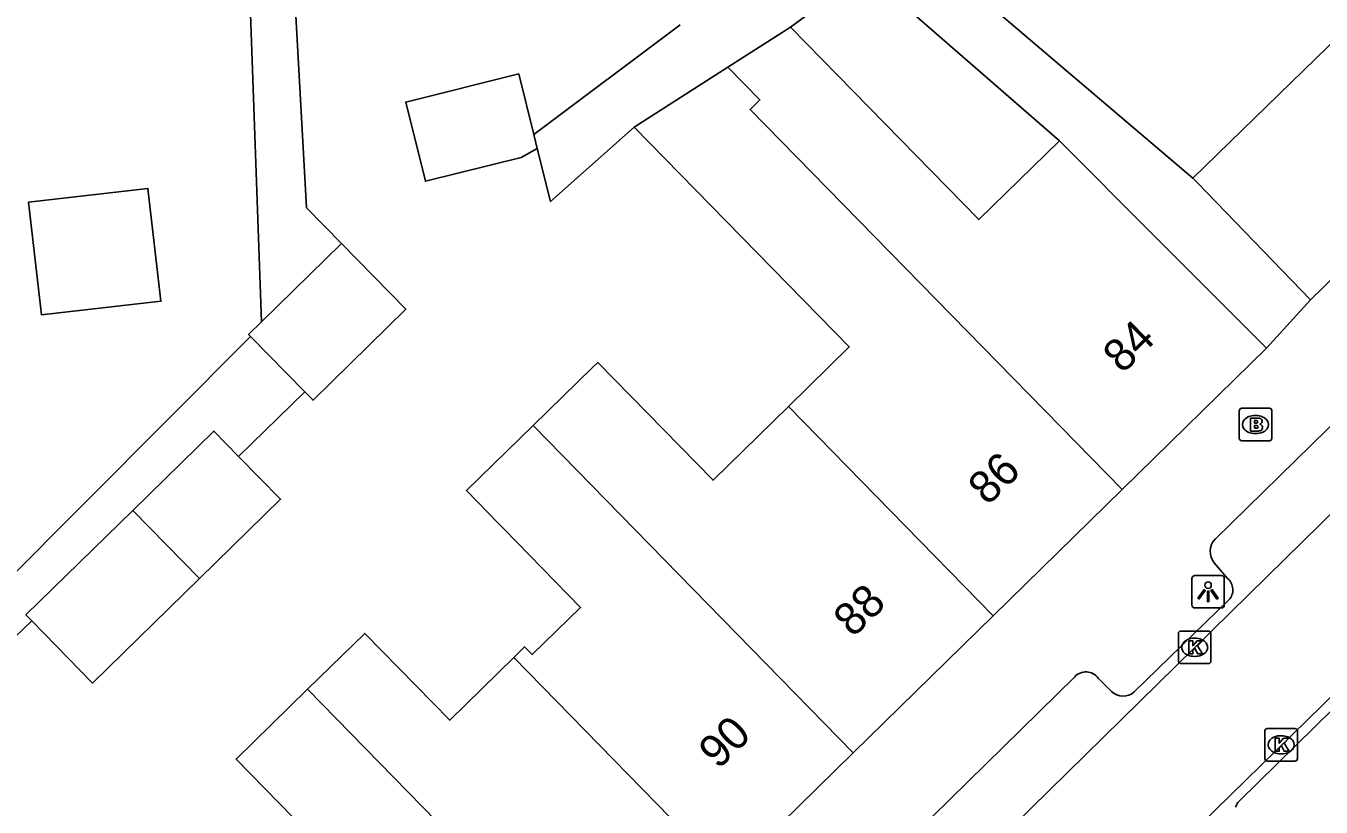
# Model space of a CAD drawing. Extents: x 160861 to 161308, y 384024 to 384878.
# Drawn here: x 161043.45 to 161083.27, y 384669.26 to 384693.28 of the extents above; entities that cross this region are included whole.
import ezdxf

# ---------------------------------------------------------------- set-up
doc = ezdxf.new("R2010")
doc.units = 0
for name, color, linetype in [('IMGEO_Brandkraan', 7, 'Continuous'), ('IMGEO_Kolk', 7, 'Continuous'), ('IMGEO_Lichtpunt', 7, 'Continuous'), ('IMGEO_Pand', 7, 'Continuous'), ('IMGEO_Pand_nummerreeks', 7, 'Continuous'), ('IMGEO_Rijbaan_lokaal_gesloten', 7, 'Continuous'), ('IMGEO_Voetpad_open', 7, 'Continuous')]:
    doc.layers.add(name, color=color, linetype=linetype)

msp = doc.modelspace()

# ---------------------------------------------------------------- linework, layer by layer
at = {"layer": 'IMGEO_Brandkraan'}
for p, q in [((161080.753, 384680.596), (161080.753, 384681.448)), ((161080.828, 384681.522), (161081.68, 384681.522)), ((161081.754, 384681.448), (161081.754, 384680.596)), ((161081.241, 384681.302), (161081.266, 384681.302)), ((161081.264, 384680.742), (161081.239, 384680.742)), ((161081.68, 384680.522), (161080.828, 384680.522))]:
    msp.add_line(p, q, dxfattribs=at)
for points in [[(161080.753, 384680.596), (161080.753, 384681.448)], [(161080.828, 384681.522), (161081.68, 384681.522)], [(161081.754, 384681.448), (161081.754, 384680.596)], [(161081.101, 384681.222), (161081.101, 384680.822), (161081.314, 384680.822)], [(161081.332, 384681.222), (161081.101, 384681.222)], [(161081.28, 384681.141), (161081.226, 384681.141), (161081.226, 384681.065)], [(161081.226, 384681.065), (161081.279, 384681.065)], [(161081.288, 384680.989), (161081.226, 384680.989), (161081.226, 384680.908)], [(161081.226, 384680.908), (161081.288, 384680.908)], [(161081.68, 384680.522), (161080.828, 384680.522)]]:
    msp.add_lwpolyline(points, dxfattribs=at)
for centre, radius, start, end in [((161080.83, 384681.446), 0.0765, 91.552, 178.448), ((161080.83, 384681.446), 0.0765, 91.552, 178.448), ((161081.678, 384681.446), 0.0765, 1.552, 88.448), ((161081.678, 384681.446), 0.0765, 1.552, 88.448), ((161081.281, 384681.103), 0.0379, 267.8285, 90.9355), ((161081.336, 384681.077), 0.145, 59.4692, 91.5367), ((161081.361, 384681.124), 0.0922, 285.5137, 58.1501), ((161081.366, 384680.932), 0.105, 301.3115, 78.989), ((161080.83, 384680.598), 0.0765, 181.552, 268.448), ((161080.83, 384680.598), 0.0765, 181.552, 268.448), ((161081.289, 384680.948), 0.0404, 269.8759, 90.5077), ((161081.32, 384681.073), 0.251, 268.6676, 293.5347), ((161081.678, 384680.598), 0.0765, 271.552, 358.448), ((161081.678, 384680.598), 0.0765, 271.552, 358.448)]:
    msp.add_arc(centre, radius, start, end, dxfattribs=at)
for centre, major_axis, ratio, start_param, end_param in [((161081.24, 384681.022), (-0.387, 0.002), 0.722429, 4.712389, 7.853982), ((161081.265, 384681.022), (-0.39, 0.002), 0.717154, 1.570796, 4.712389)]:
    msp.add_ellipse(centre, major_axis=major_axis, ratio=ratio, start_param=start_param, end_param=end_param, dxfattribs=at)
at = {"layer": 'IMGEO_Kolk'}
for p, q in [((161078.956, 384674.674), (161079.808, 384674.674)), ((161078.881, 384673.748), (161078.881, 384674.6)), ((161079.369, 384674.454), (161079.394, 384674.454)), ((161079.882, 384674.6), (161079.882, 384673.748)), ((161079.392, 384673.894), (161079.367, 384673.894)), ((161079.808, 384673.674), (161078.956, 384673.674)), ((161081.539, 384670.751), (161081.539, 384671.603)), ((161081.614, 384671.677), (161082.466, 384671.677)), ((161082.027, 384671.457), (161082.052, 384671.457)), ((161082.54, 384671.603), (161082.54, 384670.751)), ((161082.466, 384670.677), (161081.614, 384670.677)), ((161082.05, 384670.897), (161082.025, 384670.897))]:
    msp.add_line(p, q, dxfattribs=at)
for points in [[(161078.956, 384674.674), (161079.808, 384674.674)], [(161078.881, 384673.748), (161078.881, 384674.6)], [(161079.202, 384674.374), (161079.325, 384674.374), (161079.325, 384674.223), (161079.455, 384674.374), (161079.619, 384674.374), (161079.473, 384674.223), (161079.626, 384673.974), (161079.474, 384673.974), (161079.389, 384674.138), (161079.325, 384674.071), (161079.325, 384673.974), (161079.202, 384673.974), (161079.202, 384674.374)], [(161079.882, 384674.6), (161079.882, 384673.748)], [(161079.808, 384673.674), (161078.956, 384673.674)], [(161081.539, 384670.751), (161081.539, 384671.603)], [(161081.614, 384671.677), (161082.466, 384671.677)], [(161082.54, 384671.603), (161082.54, 384670.751)], [(161081.86, 384671.377), (161081.983, 384671.377), (161081.983, 384671.226), (161082.113, 384671.377), (161082.277, 384671.377), (161082.131, 384671.226), (161082.284, 384670.977), (161082.132, 384670.977), (161082.047, 384671.141), (161081.983, 384671.074), (161081.983, 384670.977), (161081.86, 384670.977), (161081.86, 384671.377)], [(161082.466, 384670.677), (161081.614, 384670.677)]]:
    msp.add_lwpolyline(points, dxfattribs=at)
for centre, start, end in [((161078.958, 384674.598), 91.552, 178.448), ((161078.958, 384674.598), 91.552, 178.448), ((161079.806, 384674.598), 1.552, 88.448), ((161079.806, 384674.598), 1.552, 88.448), ((161078.958, 384673.75), 181.552, 268.448), ((161078.958, 384673.75), 181.552, 268.448), ((161079.806, 384673.75), 271.552, 358.448), ((161079.806, 384673.75), 271.552, 358.448), ((161081.616, 384671.601), 91.552, 178.448), ((161081.616, 384671.601), 91.552, 178.448), ((161082.464, 384671.601), 1.552, 88.448), ((161082.464, 384671.601), 1.552, 88.448), ((161081.616, 384670.753), 181.552, 268.448), ((161081.616, 384670.753), 181.552, 268.448), ((161082.464, 384670.753), 271.552, 358.448), ((161082.464, 384670.753), 271.552, 358.448)]:
    msp.add_arc(centre, 0.0765, start, end, dxfattribs=at)
for centre, major_axis, ratio, start_param, end_param in [((161079.368, 384674.174), (-0.387, 0.002), 0.722429, 4.712389, 7.853982), ((161079.393, 384674.174), (-0.39, 0.002), 0.717154, 1.570796, 4.712389), ((161082.026, 384671.177), (-0.387, 0.002), 0.722429, 4.712389, 7.853982), ((161082.051, 384671.177), (-0.39, 0.002), 0.717154, 1.570796, 4.712389)]:
    msp.add_ellipse(centre, major_axis=major_axis, ratio=ratio, start_param=start_param, end_param=end_param, dxfattribs=at)
at = {"layer": 'IMGEO_Lichtpunt'}
for p, q in [((161079.295, 384676.285), (161079.295, 384675.478)), ((161079.295, 384676.285), (161079.295, 384675.478)), ((161080.197, 384676.38), (161079.389, 384676.38)), ((161080.197, 384676.38), (161079.389, 384676.38)), ((161080.291, 384675.478), (161080.291, 384676.285)), ((161080.291, 384675.478), (161080.291, 384676.285)), ((161079.389, 384675.384), (161080.197, 384675.384)), ((161079.389, 384675.384), (161080.197, 384675.384))]:
    msp.add_line(p, q, dxfattribs=at)
for points in [[(161079.669, 384675.949), (161079.708, 384675.921), (161079.52, 384675.659), (161079.482, 384675.686), (161079.669, 384675.949)], [(161079.771, 384675.901), (161079.818, 384675.901), (161079.818, 384675.579), (161079.771, 384675.579), (161079.771, 384675.901)], [(161079.881, 384675.921), (161079.919, 384675.948), (161080.106, 384675.686), (161080.067, 384675.658), (161079.881, 384675.921)]]:
    msp.add_lwpolyline(points, dxfattribs=at)
msp.add_circle((161079.794, 384676.083), 0.0994, dxfattribs=at)
for centre, start, end in [((161079.389, 384676.285), 90, 180), ((161079.389, 384676.285), 90, 180), ((161080.197, 384676.285), 0, 90), ((161080.197, 384676.285), 0, 90), ((161079.389, 384675.478), 180, 270), ((161079.389, 384675.478), 180, 270), ((161080.197, 384675.478), 270, 0), ((161080.197, 384675.478), 270, 360)]:
    msp.add_arc(centre, 0.0946, start, end, dxfattribs=at)
at = {"layer": 'IMGEO_Pand'}
for points in [[(161079.327, 384688.593), (161085.753, 384694.857)], [(161065.029, 384692.007), (161066.956, 384693.238)], [(161075.224, 384689.747), (161072.745, 384687.321), (161066.956, 384693.238)], [(161059.169, 384689.512), (161058.674, 384689.231), (161055.728, 384688.499), (161055.124, 384690.935), (161058.601, 384691.798), (161059.064, 384689.933)], [(161062.151, 384690.167), (161065.029, 384692.007)], [(161077.149, 384679.021), (161065.713, 384690.71), (161066.012, 384691.003), (161065.029, 384692.007)], [(161089.608, 384691.356), (161082.942, 384684.859)], [(161066.889, 384681.575), (161068.763, 384683.409), (161062.151, 384690.167)], [(161059.169, 384689.512), (161059.064, 384689.933)], [(161075.224, 384689.747), (161078.057, 384686.906), (161081.588, 384683.366)], [(161082.942, 384684.859), (161079.464, 384688.452), (161079.327, 384688.593)], [(161043.53, 384687.858), (161043.927, 384684.394), (161047.595, 384684.814), (161047.199, 384688.278), (161043.53, 384687.858)], [(161050.691, 384684.181), (161053.148, 384686.588)], [(161052.017, 384682.032), (161052.277, 384681.767), (161055.131, 384684.564), (161053.148, 384686.588)], [(161050.691, 384684.181), (161050.293, 384683.791), (161050.355, 384683.728)], [(161050.355, 384683.728), (161052.017, 384682.032)], [(161081.588, 384683.366), (161077.149, 384679.021)], [(161059.041, 384680.994), (161060.87, 384682.777), (161061.029, 384682.932), (161064.573, 384679.31), (161066.889, 384681.575)], [(161073.184, 384675.14), (161066.889, 384681.575)], [(161058.443, 384673.858), (161058.78, 384674.188), (161059.015, 384673.948), (161060.501, 384675.402), (161058.14, 384677.815), (161057.966, 384677.993), (161056.988, 384678.993), (161059.041, 384680.994)], [(161059.041, 384680.994), (161068.886, 384670.932)], [(161049.984, 384680.044), (161049.227, 384680.819), (161046.73, 384678.379)], [(161049.984, 384680.044), (161051.275, 384678.723), (161048.779, 384676.285)], [(161077.149, 384679.021), (161073.184, 384675.14)], [(161046.73, 384678.379), (161043.447, 384675.172), (161043.624, 384674.991)], [(161048.779, 384676.285), (161046.73, 384678.379)], [(161043.624, 384674.991), (161045.495, 384673.076), (161048.779, 384676.285)], [(161073.184, 384675.14), (161068.886, 384670.932)], [(161052.106, 384672.884), (161053.863, 384674.603), (161056.476, 384671.933), (161058.443, 384673.858)], [(161058.443, 384673.858), (161065.015, 384667.142)], [(161050.828, 384666.256), (161052.547, 384668.039), (161049.91, 384670.735), (161052.106, 384672.884)], [(161052.106, 384672.884), (161060.941, 384663.854)], [(161068.886, 384670.932), (161065.015, 384667.142)]]:
    msp.add_lwpolyline(points, dxfattribs=at)
at = {"layer": 'IMGEO_Rijbaan_lokaal_gesloten'}
for points in [[(161094.179, 384688.665), (161093.847, 384688.359), (161047.62, 384642.996), (161045.943, 384641.353)], [(161048.906, 384638.739), (161096.984, 384685.767)]]:
    msp.add_lwpolyline(points, dxfattribs=at)
at = {"layer": 'IMGEO_Voetpad_open'}
for points in [[(161050.004, 384703.409), (161050.691, 384684.181)], [(161053.148, 384686.588), (161052.077, 384687.681), (161051.522, 384697.663)], [(161079.327, 384688.593), (161070.236, 384696.337), (161069.506, 384696.104)], [(161066.956, 384693.238), (161069.256, 384694.938), (161075.224, 384689.747)], [(161059.064, 384689.933), (161063.56, 384693.314)], [(161062.151, 384690.167), (161059.576, 384687.874), (161059.169, 384689.512)], [(161080.008, 384677.5), (161091.379, 384688.627)], [(161081.588, 384683.366), (161082.942, 384684.859)], [(161050.355, 384683.728), (161027.455, 384660.754)], [(161052.017, 384682.032), (161049.984, 384680.044)], [(161080.394, 384676.293), (161079.985, 384676.767)], [(161077.524, 384672.803), (161080.434, 384675.629)], [(161043.624, 384674.991), (161041.541, 384672.986)], [(161064.172, 384661.961), (161075.693, 384673.266)], [(161076.413, 384673.228), (161076.825, 384672.82)], [(161080.64, 384669.26), (161080.653, 384669.297), (161080.669, 384669.333), (161080.688, 384669.368), (161080.71, 384669.4), (161080.735, 384669.431), (161080.763, 384669.459), (161083.642, 384672.284)]]:
    msp.add_lwpolyline(points, dxfattribs=at)
for centre, radius, start, end in [((161080.412, 384677.12), 0.554, 136.7984, 219.6072), ((161080.09, 384675.941), 0.465, 317.7259, 49.1688), ((161076.037, 384672.951), 0.467, 36.423, 137.5347), ((161077.184, 384673.183), 0.51, 225.371, 311.8426)]:
    msp.add_arc(centre, radius, start, end, dxfattribs=at)

# ---------------------------------------------------------------- texts
at = {"layer": 'IMGEO_Pand_nummerreeks'}
for s, rotation, p in [('84', 44.3892, (161077.163, 384682.56)), ('86', 44.3892, (161073.019, 384678.504)), ('88', 44.387, (161068.878, 384674.451)), ('90', 44.387, (161064.735, 384670.395))]:
    msp.add_text(s, height=1, rotation=rotation, dxfattribs=at).set_placement(p)

doc.saveas('drawing.dxf')
